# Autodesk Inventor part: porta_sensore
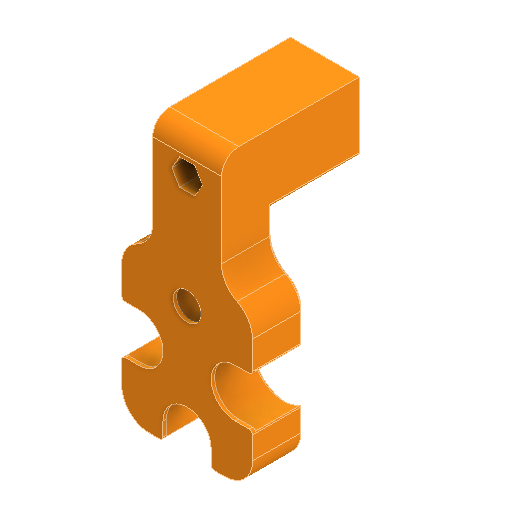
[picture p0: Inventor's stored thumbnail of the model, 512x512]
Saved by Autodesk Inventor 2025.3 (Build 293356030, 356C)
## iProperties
Created: 2025-09
Part Number: porta_sensore
Material: Plastica ABS
Document SubType Name: Modeling
Designer: Ryzen5700u
Density: 1.06 g/cm^3
Appearance: Arancione
Author: Ryzen5700u
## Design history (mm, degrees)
sketch "Schizzo1"
  geometry: L1 (-10, -96)-(-10, 38) reference; L2 (9, -97)-(-9, -97) reference; L3 (10, 38)-(10, -96) reference; L4 (10, -97)-(-10, -97); L5 (-10, -97)-(-10, -77); L6 (-10, -77)-(10, -77); L7 (10, -77)-(10, -97); L8 (-10, 38)-(10, 38) reference; C1 r 2.25 at (0, -87) reference; A1 r 1 centre (-9, -96) between (-10, -96) and (-9, -97) reference; A2 r 1 centre (9, -96) between (9, -97) and (10, -96) reference; 7 further points
  constraints: 8 end point, 2 parallel, 1 horizontal, 1 perpendicular
  dimensions: "d0" = 20 distance of L5.end L6.end; "d1" = 20 distance of L4.end L5.end
extrude "Estrusione1" new body sketch "Schizzo1" distance "d2" = 40; taper "d3" = 0 deg
sketch "Schizzo2"
  geometry: L1 (1, 40)-(19, 40) reference; L2 (20, 40)-(0, 40); L3 (0, 40)-(0, 25); L4 (0, 25)-(20, 25); L5 (20, 25)-(20, 40); 5 further points
  constraints: 8 end point, 2 parallel, 1 horizontal, 1 perpendicular
  dimensions: "d4" = 20 distance of L4.end L3.end; "d5" = 15 distance of L3.end L2.end
extrude "Estrusione2" join sketch "Schizzo2" distance "d6" = 15; taper "d7" = 0 deg
sketch "Schizzo3"
  geometry: L1 (0, -15)-(20, -15) reference; L2 (10, -15)-(10, -78.397); L3 (20, -15)-(46.316, -15); L4 (0, -15)-(-26.316, -15); L5 (29, -15)-(-9, -15); L6 (-9, -15)-(-9, -60); L7 (-9, -60)-(29, -60); L8 (29, -60)-(29, -15); L9 (-9, -37.5)-(29, -37.5); L10 (-4, -28.5)-(-9, -28.5); L11 (24, -28.5)-(29, -28.5); L12 (-4, -46.5)-(-9, -46.5); L13 (1, -55)-(1, -60); L14 (19, -55)-(19, -60); L15 (24, -46.5)-(29, -46.5); C1 r 5.5 at (10, -22.614); A1 r 9 centre (-4, -37.5) between (-4, -28.5) and (-4, -46.5); A2 r 9 centre (24, -37.5) between (24, -28.5) and (24, -46.5); A3 r 9 centre (10, -55) between (1, -55) and (19, -55); 9 further points
  constraints: 28 end point, 13 point on line, 6 perpendicular, 6 point on circle, 4 centre point, 4 tangent, 3 midpoint, 2 horizontal, 2 parallel, 1 symmetric about line, 1 vertical, 1 other
  dimensions: "d28" = 45 distance of L6.end L5.end; "d29" = 38 distance of L6.end L7.end; "d30" = 18 diameter of A1; "d31" = 18 diameter of A2; "d32" = 5 distance from line of L6 A1.centre; "d33" = 5 distance from line of L8 A2.centre; "d34" = 11 diameter of C1; "d35" = 18 diameter of A3; "d36" = 5 distance from line of L7 A3.centre
extrude "Estrusione3" join sketch "Schizzo3" distance "d16" = 15; taper "d17" = 0 deg
sketch "Schizzo4"
  geometry: L1 (10, -77)-(-10, -77) reference; 2 further points
  dimensions: "d18" = 10 distance from line of L1 point (0, -87)
hole "Foro1" sketch "Schizzo4" at (0, -87) diameter "d19" = 4.5; stored, may be unused: countersink angle "d23" = 90 deg, drill point angle "d25" = 118 deg; dims "d20" = 6, "d21" = 8, "d22" = 20, "d24" = 8
sketch "Schizzo5"
  geometry: L1 (-10, -77)-(-10, -96) reference; L2 (-10, -112)-(-19, -112) reference; L3 (-19, -112)-(-19, -127.017) reference; L4 (-19, -141.983)-(-19, -157) reference; L5 (-19, -157)-(-7.483, -157) reference; L6 (7.483, -157)-(19, -157) reference; L7 (19, -157)-(19, -141.983) reference; L8 (19, -127.017)-(19, -112) reference; L9 (19, -112)-(10, -112) reference; L10 (10, -97)-(10, -112) reference; L11 (-14, -141.5)-(-19, -141.5); L12 (-19, -141.5)-(-19, -143.5); L13 (-14, -127.5)-(-19, -127.5); L14 (-19, -127.5)-(-19, -125.5); L15 (14, -127.5)-(19, -127.5); L16 (19, -127.5)-(19, -125.5); L17 (14, -141.5)-(19, -141.5); L18 (19, -143.5)-(19, -141.5); L19 (7, -152)-(7, -157); L20 (7, -157)-(9, -157); L21 (-7, -152)-(-7, -157); L22 (-7, -157)-(-9, -157); L23 (-9, -97)-(-10, -97) reference; L24 (-10, -97)-(-10, -112) reference; L25 (10, -97)-(9, -97) reference; L26 (10, -96)-(10, -77) reference; L27 (10, -77)-(-10, -77) reference; C1 r 5.5 at (0, -119.614) reference; C2 r 4 at (0, -119.614); A1 r 9 centre (-14, -134.5) between (-19, -141.983) and (-19, -127.017) reference; A2 r 9 centre (0, -152) between (7.483, -157) and (-7.483, -157) reference; A3 r 9 centre (14, -134.5) between (19, -127.017) and (19, -141.983) reference; A4 r 7 centre (0, -152) between (7, -152) and (-7, -152); A5 r 7 centre (-14, -134.5) between (-14, -141.5) and (-14, -127.5); A6 r 7 centre (14, -134.5) between (14, -127.5) and (14, -141.5); A7 r 1 centre (-9, -96) between (-10, -96) and (-9, -97) reference; A8 r 1 centre (9, -96) between (9, -97) and (10, -96) reference; 8 further points
  constraints: 24 end point, 8 point on line, 7 perpendicular, 6 point on circle, 4 centre point, 4 coincident, 4 tangent, 1 horizontal, 1 parallel
  dimensions: "d37" = 14 diameter of A4; "d38" = 14 diameter of A5; "d39" = 14 diameter of A6; "d40" = 8 diameter of C2
extrude "Estrusione4" join sketch "Schizzo5" distance "d41" = 1; taper "d42" = 0 deg
fillet "Raccordo3" dims "d43" = 8
chamfer "Smusso1" distance "d44" = 1; stored, may be unused: second distance "d45" = 2, angle "d46" = 45 deg
fillet "Raccordo4" dims "d47" = 1
sketch "Schizzo6"
  geometry: L1 (4.4, -87)-(2.2, -90.811); L2 (2.2, -90.811)-(-2.2, -90.811); L3 (-2.2, -90.811)-(-4.4, -87); L4 (-4.4, -87)-(-2.2, -83.189); L5 (-2.2, -83.189)-(2.2, -83.189); L6 (2.2, -83.189)-(4.4, -87); C1 r 2.25 at (0, -87) reference; 2 further points
  constraints: 12 end point, 13 other
  dimensions: "d51" = 4.4 distance of L1.end L2.end
extrude "Estrusione5" cut sketch "Schizzo6" distance "d48" = 20; taper "d49" = 0 deg
fillet "Raccordo5" dims "d52" = 2
fillet "Raccordo6" dims "d53" = 5
sketch "Schizzo7"
  geometry: L1 (10, -82)-(10, -96) reference; L2 (-10, -97)-(-10, -104) reference; L3 (10, -95.297)-(-10, -95.297); L4 (-10, -95.297)-(-10, -97); L5 (-10, -97)-(10, -97); L6 (10, -97)-(10, -95.297); 2 further points
  constraints: 8 end point, 2 parallel, 1 horizontal, 1 perpendicular, 1 point on line
extrude "Estrusione6" join sketch "Schizzo7" stored distance "d54" = 15; taper "d55" = 0 deg
fillet "Raccordo7" dims "d56" = 5
fillet "Raccordo8" dims "d57" = 1
node "Solido1"
node "Riferimento1"
node "Linea chiusa proiettata1"
